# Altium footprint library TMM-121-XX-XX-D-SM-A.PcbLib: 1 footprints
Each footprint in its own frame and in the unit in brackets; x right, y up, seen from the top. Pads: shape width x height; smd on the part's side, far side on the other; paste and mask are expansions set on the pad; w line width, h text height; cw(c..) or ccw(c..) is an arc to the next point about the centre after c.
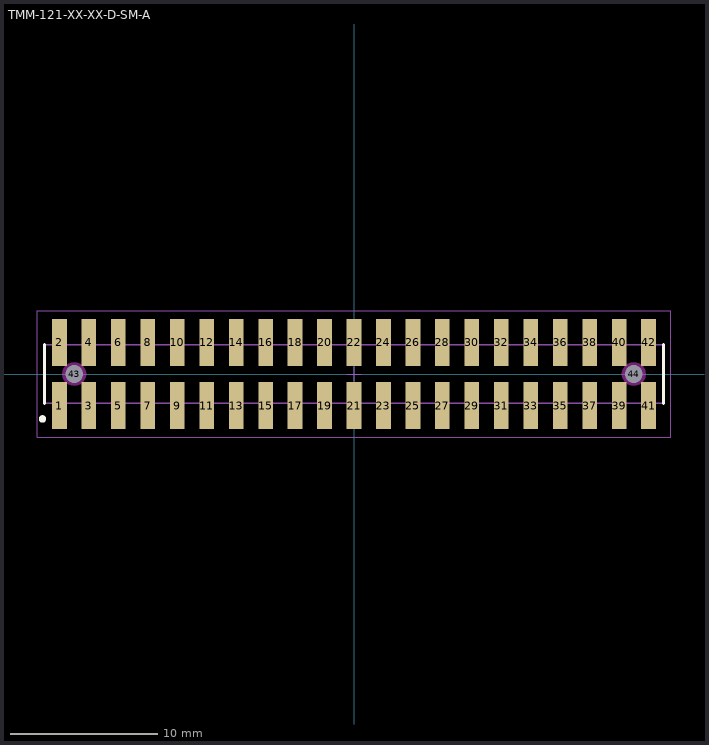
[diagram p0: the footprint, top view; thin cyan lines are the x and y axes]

## TMM-121-XX-XX-D-SM-A [mm] "2.00mm pitch, 42 pin, terminal strip; double row, w/alignment pins, SMT"
height 2.77
pads (44):
  rect 1x3.2 smd mask+0: 1(-20,-2.15) 2(-20,2.15) 3(-18,-2.15) 4(-18,2.15) 5(-16,-2.15) 6(-16,2.15) 7(-14,-2.15) 8(-14,2.15) 9(-12,-2.15) 10(-12,2.15) 11(-10,-2.15) 12(-10,2.15) 13(-8,-2.15) 14(-8,2.15) 15(-6,-2.15) 16(-6,2.15) 17(-4,-2.15) 18(-4,2.15) 19(-2,-2.15) 20(-2,2.15) 21(0,-2.15) 22(0,2.15) 23(2,-2.15) 24(2,2.15) 25(4,-2.15) 26(4,2.15) 27(6,-2.15) 28(6,2.15) 29(8,-2.15) 30(8,2.15) 31(10,-2.15) 32(10,2.15) 33(12,-2.15) 34(12,2.15) 35(14,-2.15) 36(14,2.15) 37(16,-2.15) 38(16,2.15) 39(18,-2.15) 40(18,2.15) 41(20,-2.15) 42(20,2.15)
  round 1 hole 1.2 unplated mask+0: 43(-19,0) 44(19,0)
Top Overlay:
  circle w0.25: c-21.15,-3.05 r0.125
  lines w0.2: -21,-2 -21,2 ; 21,-2 21,2
Keep-Out Layer:
  pour cut-out: -18.193,0 -18.221,0.209 -18.301,0.403 -18.429,0.571 -18.597,0.699 -18.791,0.779 -19,0.807 -19.209,0.779 -19.403,0.699 -19.571,0.571 -19.699,0.403 -19.779,0.209 -19.807,0 -19.779,-0.209 -19.699,-0.403 -19.571,-0.571 -19.403,-0.699 -19.209,-0.779 -19,-0.807 -18.791,-0.779 -18.597,-0.699 -18.429,-0.571 -18.301,-0.403 -18.221,-0.209
  pour cut-out: 19.807,0 19.779,0.209 19.699,0.403 19.571,0.571 19.403,0.699 19.209,0.779 19,0.807 18.791,0.779 18.597,0.699 18.429,0.571 18.301,0.403 18.221,0.209 18.193,0 18.221,-0.209 18.301,-0.403 18.429,-0.571 18.597,-0.699 18.791,-0.779 19,-0.807 19.209,-0.779 19.403,-0.699 19.571,-0.571 19.699,-0.403 19.779,-0.209
Mechanical 12:
  lines w0.001: -21,-2 21,-2 21,2 -21,2 -21,-2
Mechanical 13:
  lines w0.1: -21,-2 21,-2 21,2 -21,2 -21,-2
  text ".Designator" at 0,-0.127 h1.52
Mechanical 15:
  lines w0.05: -0.5,0 0.5,0 ; 0,-0.5 0,0.5 ; -21.5,-4.3 21.5,-4.3 21.5,4.3 -21.5,4.3 -21.5,-4.3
